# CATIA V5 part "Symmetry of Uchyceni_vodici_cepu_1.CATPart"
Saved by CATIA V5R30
Part number: Uchyceni_vodici_cepu_1
Bounding box of the stored display mesh (mm): x -14.5 to 8.5, y -20 to 20, z 0 to 24
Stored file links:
  E:\Bakalarka\Model\Forma_v7\Symmetry of Uchyceni_vodici_cepu_1.CATPart
  E:\Bakalarka\Model\Chyba catie 2\Uchyceni_vodici_cepu_1.CATPart
  E:\Bakalarka\Model\Forma_v7\Slider_1.CATProduct
  E:\Bakalarka\Model\Forma_v7\Forma_Slider_1_1.CATPart
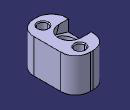
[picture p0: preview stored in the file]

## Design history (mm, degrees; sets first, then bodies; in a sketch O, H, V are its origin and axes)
Body1 (main body)
  Body2 "Body from original PartBody"
    Solid1: linked copy from another document
  Assemble1: tool Body2
  Body3 "Result of DrillHole"
    Solid2: linked copy from another document
  Assemble2 "DrillHoleCapScrew_E1200_1.5": tool Body3
  Body4 "Result of DrillHole"
    Solid3: linked copy from another document
  Assemble3 "DrillHoleCapScrew_E1200_1.6": tool Body4
  Body5 "Result of DrillHole"
    Solid4: linked copy from another document
  Assemble4 "DrillHoleCapScrew_E1200_1.7": tool Body5
  Body6 "Result of DrillHole"
    Solid5: linked copy from another document
  Assemble5 "DrillHoleCapScrew_E1200_1.8": tool Body6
